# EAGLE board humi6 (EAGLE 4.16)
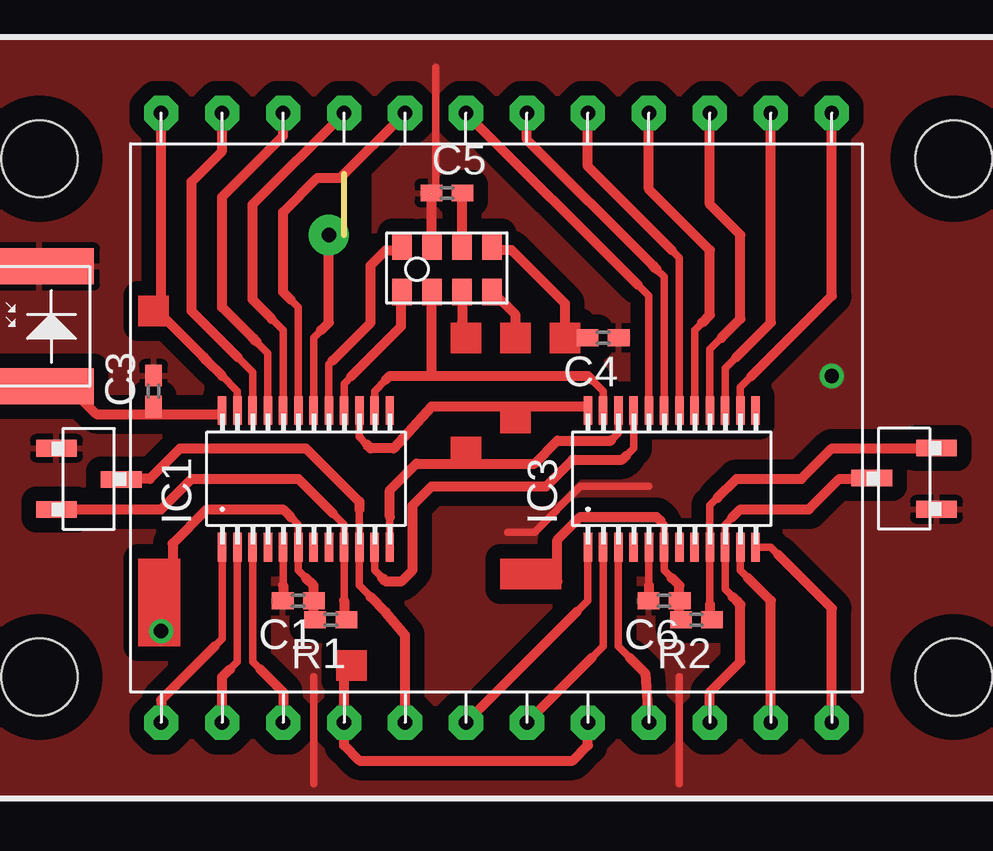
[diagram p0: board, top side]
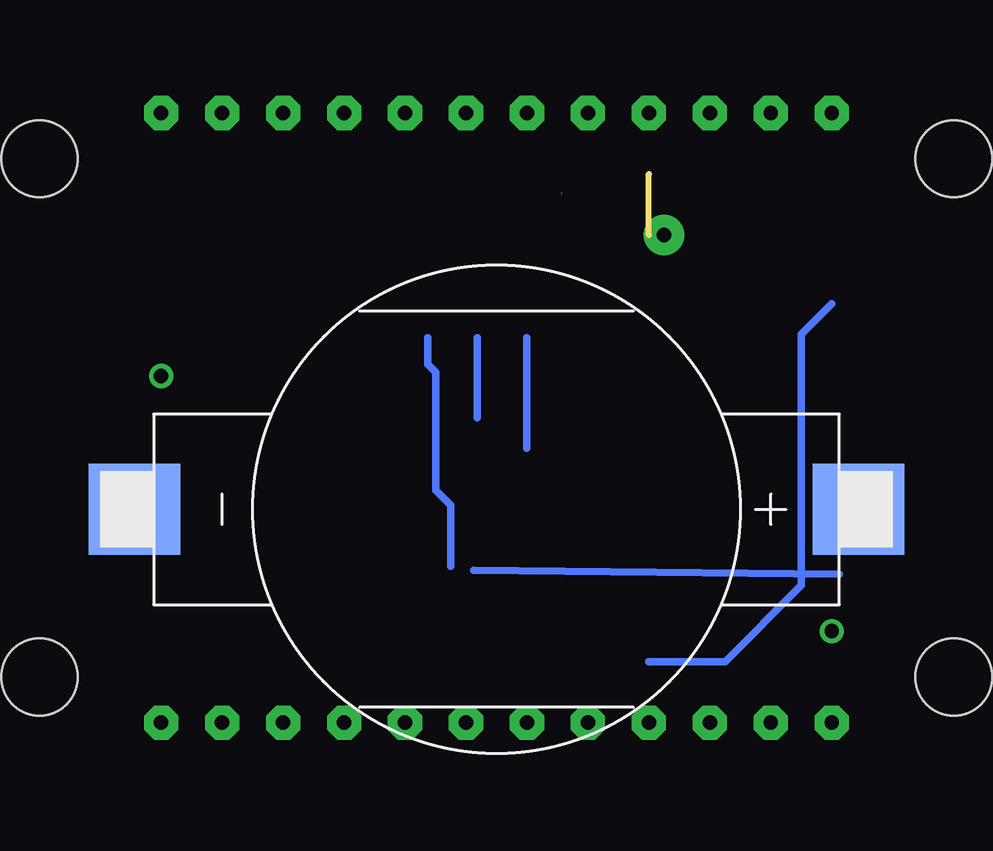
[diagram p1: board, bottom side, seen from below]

Size 0 x 2.54 mm. Coordinates in mm from the lower left corner, seen from the top.
Outline: 0,0 0,2.54
Copper layers (1*16): Top 0.035mm / dielectric 1.5mm / Bottom 0.035mm
Design rules "default": minimum track width 10mil, minimum drill 24mil, track to track 8mil, track to pad 8mil, pad to pad 8mil, via to via 8mil, smd to smd 8mil, copper to edge 40mil, drill to drill 8mil, minimum pad ring 10mil, minimum via ring 8mil, stop-mask expansion 4mil, vias tented up to drill 0mil, thermal gap 10mil
Holes 3.2 mm at -12.7,3.18 -12.7,-18.41 25.4,-18.41 25.4,3.18

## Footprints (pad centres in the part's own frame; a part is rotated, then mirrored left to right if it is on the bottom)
C0402 = smd 0.9 x 0.7: 1 -0.65,0; 2 0.65,0
TEMD = smd 4.55 x 1.5: P$1 0,2.5; P$2 0,-2.5
VI321 = drill 0.6 pad 1.422 octagon: 1 -13.97,-12.7; 2 -11.43,-12.7; 3 -8.89,-12.7; 4 -6.35,-12.7; 5 -3.81,-12.7; 6 -1.27,-12.7; 7 1.27,-12.7; 8 3.81,-12.7; 9 6.35,-12.7; 10 8.89,-12.7; 11 11.43,-12.7; 12 13.97,-12.7; 13 13.97,12.7; 14 11.43,12.7; 15 8.89,12.7; 16 6.35,12.7; 17 3.81,12.7; 18 1.27,12.7; 19 -1.27,12.7; 20 -3.81,12.7; 21 -6.35,12.7; 22 -8.89,12.7; 23 -11.43,12.7; 24 -13.97,12.7
HEADER3S = smd 0.7 x 1.7: P$1 1.27,1.35; P$3 -1.28,1.35; P$4 -0.03,-1.35
MPL115A2 = smd 1.1 x 0.8: P$1 -0.95,-0.625; P$2 -0.95,0.625; P$3 -0.95,1.875; P$4 -0.95,-1.875; P$5 0.95,-1.875; P$6 0.95,-0.625; P$7 0.95,0.625; P$8 0.95,1.875
CR2032 = smd 3.8 x 3.8: P$2 0,15.081; P$3 0,-15.081
QSOP24 = smd 1.2 x 0.35: P$1 -2.849,3.81; P$2 -2.849,3.175; P$3 -2.849,2.54; P$4 -2.849,1.905; P$5 -2.849,1.27; P$6 -2.849,0.635; P$7 -2.849,0; P$8 -2.849,-0.635; P$9 -2.849,-1.27; P$10 -2.849,-1.905; P$11 -2.849,-2.54; P$12 -2.849,-3.175; P$13 2.849,-3.175; P$14 2.849,-2.54; P$15 2.849,-1.905; P$16 2.849,-1.27; P$17 2.849,-0.635; P$18 2.849,0; P$19 2.849,0.635; P$20 2.849,1.27; P$21 2.849,1.905; P$22 2.849,2.54; P$23 2.849,3.175; P$24 2.849,3.81

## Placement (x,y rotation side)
C1  [C0402]  not placed on the board
C3  [C0402]  not placed on the board
C4  [C0402]  not placed on the board
C5  [C0402]  4.29,1.75 0 top  (outside the outline)
C6  [C0402]  not placed on the board
D1  [TEMD]  not placed on the board
E$4  [VI321]  6.35,-7.62 0 top
E$5  [HEADER3S]  not placed on the board
E$6  [HEADER3S]  not placed on the board
E$10  [MPL115A2]  4.29,-1.43 270 top
E$16  [CR2032]  not placed on the board
IC1  [QSOP24]  not placed on the board
IC3  [QSOP24]  not placed on the board
R1  [C0402]  not placed on the board
R2  [C0402]  not placed on the board

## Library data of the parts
C1 C3-C6 R1 R2 = ref-packages
D1 E$5 E$6 E$10 E$16 IC1 IC3 = sb
E$4 = display-lcd

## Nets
GND: C1.2 C3.2 C4.1 C5.1 C6.2 D1.P$1 E$5.P$1 E$6.P$1

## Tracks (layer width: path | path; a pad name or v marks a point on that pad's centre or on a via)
GND  (via drill 0.6)  (1 unrouted)
  Top 0.305: -1.27,-22.86 -1.27,-18.41 | -2.54,-14.6 -2.54,-12.7 | 12.7,-14.6 12.7,-12.7 | 13.97,-22.86 13.97,-18.41 | 3.65,1.75 3.81,1.91 3.81,6.98 | 6.83,-12.38 7.94,-12.38 9.84,-10.48 12.7,-10.48
  Top 0.406: -2.54,-14.6 -2.54,-15.24 | 12.7,-14.6 12.7,-15.24 | 3.65,-0.48 3.65,1.75
  other vias: 20.32,-5.87
  pour Top (isolate 0.61): 30.48,-23.49 -17.78,-23.49 -17.78,6.67 -17.78,6.83 -17.78,8.25 30.48,8.25
S$1
  Top 0.305: 15.24,-15.4 15.24,-11.27 15.56,-10.95
  Top 0.406: 15.24,-15.4 15.24,-15.87 | 15.56,-10.95 16.35,-10.16 19.05,-10.16 20.32,-8.89 24.13,-8.89
S$2  (via drill 0.6)
  other vias: -12.7,-18.41
S$3
  Top 0.305: 1.27,-7.14 1.27,-6.51 1.75,-6.03 | 10.32,-6.03 10.79,-6.51 10.79,-7.3
  Top 0.406: 1.75,-6.03 | 1.75,-6.03 1.9,-5.87 10.16,-5.87 10.32,-6.03
S$4
  Top 0.305: 16.51,-7.46 16.51,-6.35 16.99,-5.87
  Top 0.406: 20.32,5.08 20.32,-2.54 16.99,-5.87
S$5
  Top 0.305: 15.88,-12.7 15.88,-12.06 16.19,-11.75
  Top 0.406: 16.19,-11.75 16.51,-11.43 19.37,-11.43 20.64,-10.16 22.07,-10.16
S$6
  Top 0.305: 1.27,-13.33 1.27,-13.97 1.59,-14.29 | 11.75,-9.21 12.06,-8.89 12.06,-7.62
  Top 0.406: 2.38,-14.45 | 2.38,-14.45 1.75,-14.45 1.59,-14.29 | 2.38,-14.45 2.86,-13.97 2.86,-11.27 3.65,-10.48 8.41,-10.48 9.52,-9.37 11.59,-9.37 11.75,-9.21
S$7
  Top 0.305: 1.9,-11.75 1.9,-12.7 | 11.11,-8.57 11.43,-8.25 11.43,-7.62
  Top 0.406: 1.9,-11.75 1.9,-10.64 3.02,-9.52 7.94,-9.52 8.89,-8.57 11.11,-8.57
S$8
  Top 0.305: 0.63,-7.62 0.63,-8.41 0.95,-8.73
  Top 0.406: 0.95,-8.73 1.11,-8.89 2.06,-8.89 | 2.06,-8.89 | 10,-7.14 9.68,-7.14 4.13,-7.14 3.65,-7.14 | 2.06,-8.89 3.65,-7.14 | 3.65,-7.14
S$9
  Top 0.305: 16.35,-5.08 15.88,-5.56 15.88,-7.62
  Top 0.406: 16.35,-5.08 17.78,-3.65 17.78,5.08
S$10
  Top 0.305: 15.72,-4.29 15.24,-4.76 15.24,-7.46
  Top 0.406: 15.24,5.08 15.24,1.27 16.51,0 16.51,-3.49 15.72,-4.29
S$11
  Top 0.305: 14.6,-7.62 14.6,-3.97 14.92,-3.65
  Top 0.406: 12.7,5.08 12.7,1.91 14.29,0.32 15.24,-0.63 15.24,-3.33 14.92,-3.65
S$12
  Top 0.305: 13.65,-0.63 13.97,-0.95 13.97,-7.62
  Top 0.406: 13.65,-0.63 10.16,2.86 10.16,5.08
S$13
  Top 0.305: 16.19,-15.08 15.88,-14.76 15.88,-13.33
  Top 0.406: 15.24,-20.32 15.24,-19.05 16.51,-17.78 16.51,-15.4 16.35,-15.24 16.19,-15.08
S$14
  Top 0.305: 13.02,-1.43 13.33,-1.75 13.33,-7.62
  Top 0.406: 7.62,5.08 7.62,3.97 12.86,-1.27 13.02,-1.43
S$15
  Top 0.305: 12.22,-2.06 12.7,-2.54 12.7,-7.46
  Top 0.406: 12.22,-2.06 5.08,5.08
S$16
  Top 0.305: -1.27,-7.46 -1.27,-4.29 -0.95,-3.97
  Top 0.406: -0.95,-3.97 -0.64,-3.65 -0.64,0 | -0.64,0
S$17
  Top 0.305: -2.22,-2.7 -1.91,-3.02 -1.91,-7.46
  Top 0.406: -2.22,-2.7 -2.38,-2.54 -2.54,-2.38 -2.54,0.95 -1.11,2.38 -0.16,2.38 2.54,5.08
S$18
  Top 0.305: -2.54,-7.46 -2.54,-3.97 -3.02,-3.49
  Top 0.406: -3.02,-3.49 -3.81,-2.7 -3.81,1.27 0,5.08
S$19
  Top 0.305: -3.65,-4.45 -3.18,-4.92 -3.18,-7.62
  Top 0.406: -3.65,-4.45 -3.81,-4.29 -5.08,-3.02 -5.08,1.59 -2.54,4.13 -2.54,5.08
S$20
  Top 0.305: 0.63,-11.43 0.63,-12.7
  Top 0.406: -8.89,-10.16 -8.1,-10.16 -6.83,-8.89 -1.59,-8.89 0.63,-11.11 0.63,-11.43
S$21
  Top 0.305: -4.45,-5.08 -3.81,-5.71 -3.81,-7.62
  Top 0.406: -4.45,-5.08 -6.35,-3.18 -6.35,2.22 -5.08,3.49 -5.08,5.08
S$22
  Top 0.406: 0,-18.1 0,-21.27 0.63,-21.91 9.52,-21.91 10.16,-21.27 10.16,-20.32
S$23
  Top 0.305: 18.1,-13.33 17.78,-13.02 17.14,-13.02
  Top 0.406: 20.32,-20.32 20.32,-15.56 18.1,-13.33
S$24
  Top 0.305: 16.83,-14.29 16.51,-13.97 16.51,-12.7
  Top 0.406: 17.78,-20.32 17.78,-15.24 16.83,-14.29
S$26
  Top 0.305: 11.91,-17.62 11.43,-17.14 11.43,-12.86
  Top 0.406: 12.7,-20.32 12.54,-18.26 11.91,-17.62
S$27
  Top 0.305: -0.48,-11.59 0,-12.06 0,-15.24
  Top 0.406: -11.43,-11.43 -7.62,-11.43 -6.35,-10.16 -1.91,-10.16 -0.48,-11.59 | 0,-15.24 0,-15.87
S$28
  Bottom 0.305: -7.94,-14.13 7.3,-13.97
S$29  (via drill 0.6)
  other vias: -12.7,3.18
S$30
  Top 0.305: -2.22,-11.75 -1.91,-12.06 -1.91,-13.02
  Top 0.406: -7.14,-13.97 -7.14,-12.86 -5.72,-11.43 -2.54,-11.43 -2.22,-11.75
S$31  (via drill 0.6)
  other vias: 25.4,3.18
S$32  (via drill 0.6)
  other vias: 25.4,-18.41
S$33  (via drill 0.6 pad 1.68)
  other vias: -0.64,0
S$34
  Top 0.305: 10.32,-17.62 10.79,-17.14 10.79,-12.86
  Top 0.406: 7.62,-20.32 10.32,-17.62
S$35
  Top 0.305: -0.64,-6.98 -0.64,-5.4 -0.48,-5.24
  Top 0.406: -0.48,-5.24 1.11,-3.65 1.11,-1.27 1.75,-0.63 2.54,-0.63
S$36  (via drill 0.6)
  other vias: -7.62,-16.51
S$37
  Top 0.305: 9.68,-15.72 10.16,-15.24 10.16,-12.7
  Top 0.406: 5.08,-20.32 9.68,-15.72
S$38
  Top 0.305: -5.08,-5.87 -4.45,-6.51 -4.45,-6.98
  Top 0.406: -5.08,-5.87 -5.72,-5.24 -5.87,-5.08 -7.62,-3.33 -7.62,-2.54 -7.62,5.08
S$39
  Top 0.305: 1.11,-15.08 0.63,-14.6 0.63,-12.86
  Top 0.406: 1.11,-15.08 1.75,-15.72 2.54,-16.67 2.54,-20.32
S$40
  Top 0.406: -5.24,-7.46 -10.32,-7.46 -11.43,-6.35
S$41
  Top 0.305: -3.49,-18.1 -3.81,-17.78 -3.81,-12.7
  Top 0.406: -2.54,-20.32 -2.54,-19.05 -3.49,-18.1
S$42
  Top 0.305: -4.76,-18.1 -4.45,-17.78 -4.45,-12.7
  Top 0.406: -5.08,-20.32 -5.08,-18.41 -4.76,-18.1
S$43
  Top 0.305: -5.4,-17.14 -5.08,-16.83 -5.08,-12.7
  Top 0.406: -7.62,-20.32 -7.62,-19.37 -5.4,-17.14
S$44
  Top 0.305: 0,-7.62 0,-6.35 0,-6.19 0.32,-5.87
  Top 0.406: 0.32,-5.87 2.38,-3.81 2.38,-3.18 2.38,-2.38 2.54,-2.38
S$45
  Top 0.406: 6.19,-2.38 7.14,-3.33 7.14,-3.81
S$46
  Top 0.305: -1.91,-12.7 -1.91,-13.97 -1.59,-14.29
  Top 0.406: -1.59,-14.29 -1.27,-14.6 -1.27,-15.24 -1.27,-15.87
S$47
  Top 0.305: 13.33,-12.7 13.33,-13.97 13.65,-14.29
  Top 0.406: 13.65,-14.29 13.97,-14.6 13.97,-15.95
S$48
  Top 0.406: 3.65,-5.87 3.65,-2.06
S$49
  Bottom 0.305: 0,-17.78 -3.18,-17.78 -6.35,-14.6 -6.35,-4.13 -7.62,-2.86
S$56
  Top 0.406: 4.92,-2.7 4.92,-3.65
S$57
  Bottom 0.305: 7.14,-7.62 7.14,-4.29
S$58
  Top 0.406: 6.35,-0.63 6.98,-0.63 9.21,-2.86 9.21,-4.29
S$60
  Top 0.406: 4.92,-0.16 4.92,1.75
S$61
  Bottom 0.305: 5.08,-8.89 5.08,-4.29
S$62
  Top 0.305: 13.18,-11.91 13.33,-12.06 13.33,-13.02
  Top 0.406: 8.89,-14.45 8.89,-12.7 9.84,-11.75 13.02,-11.75 13.18,-11.91
S$63
  Bottom 0.305: 8.25,-13.81 8.25,-11.27 8.89,-10.64 8.89,-5.71 9.21,-5.4 9.21,-4.29
(copper drawn outside any net)
  shapes: Top area x9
